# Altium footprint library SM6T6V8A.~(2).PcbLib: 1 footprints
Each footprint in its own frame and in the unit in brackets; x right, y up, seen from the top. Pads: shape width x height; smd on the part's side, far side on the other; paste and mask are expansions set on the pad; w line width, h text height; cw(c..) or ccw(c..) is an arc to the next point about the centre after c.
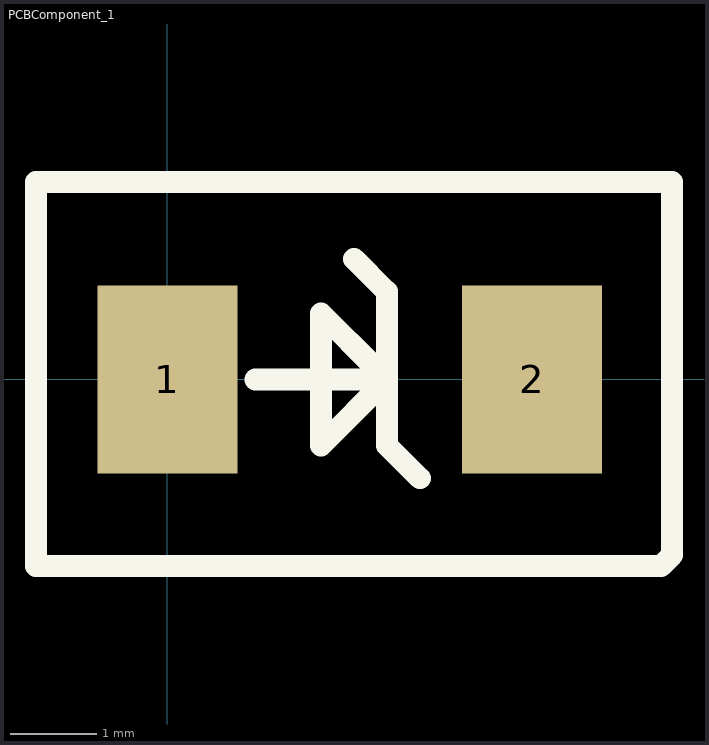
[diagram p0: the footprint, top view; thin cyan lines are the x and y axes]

## PCBComponent_1 [mm]
pads (2):
  rect 1.62x2.18 all layers, no hole: 1(0,0) 2(4.22,0)
Top Overlay:
  lines w0.254: 1.016,0 2.286,0 ; 2.159,1.397 2.54,1.016 2.54,0.889 2.54,-0.762 2.921,-1.143 ; -1.524,-2.159 5.715,-2.159 5.842,-2.032 5.842,2.286 -1.524,2.286 -1.524,-2.159 ; 1.778,-0.762 1.778,0.762 2.413,0.127 2.54,0.127 2.54,0 1.778,-0.762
